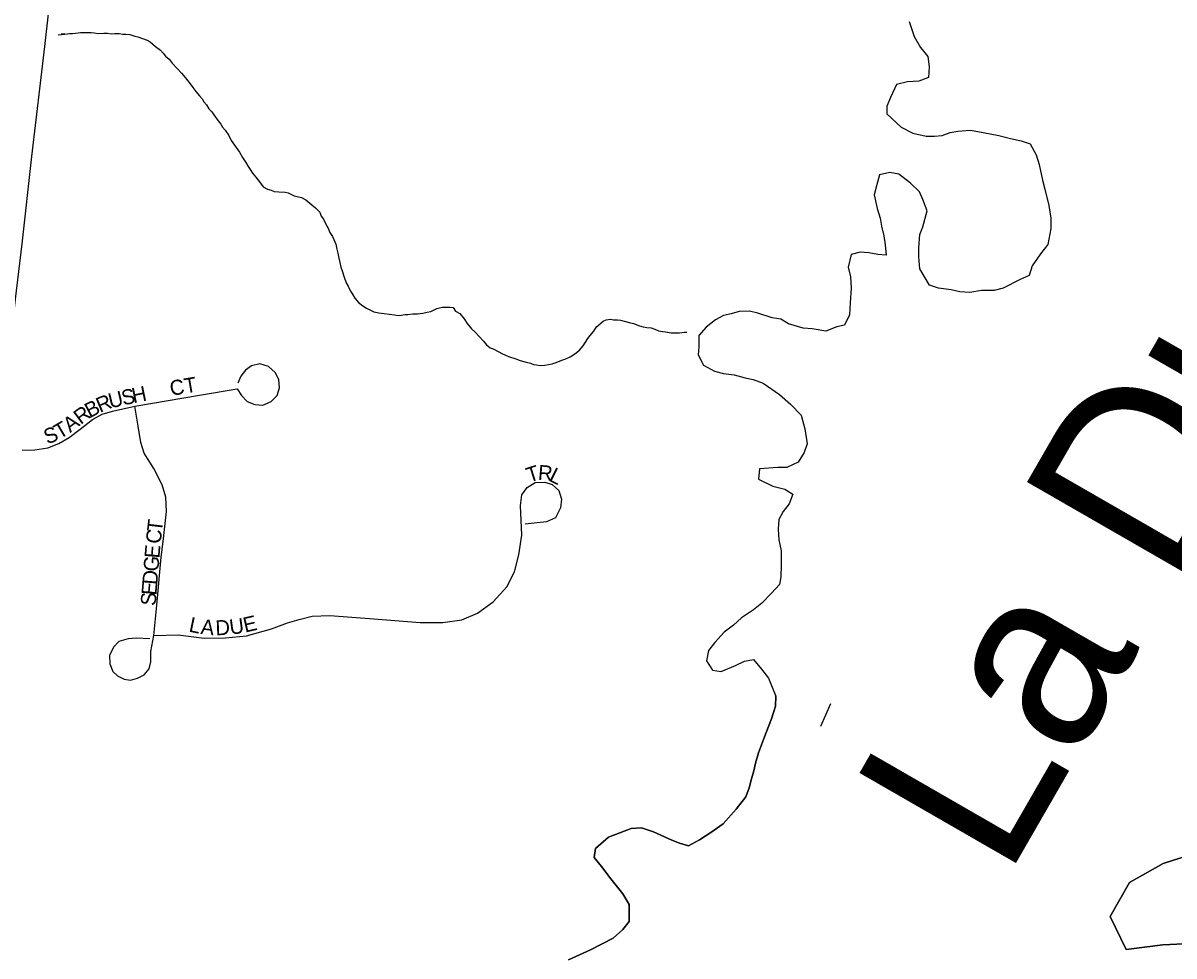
# Model space of a CAD drawing. Extents: x 0 to 34, y 0 to 22.
# Drawn here: x 3.05 to 3.775, y 16 to 16.588 of the extents above; entities that cross this region are included whole.
import ezdxf

# ---------------------------------------------------------------- set-up
doc = ezdxf.new("R2010")
doc.units = 0
for name, color, linetype in [('GM_X_Major_Lake', 7, 'Continuous'), ('GM_X_Major_Lake_Text', 7, 'Continuous'), ('GM_X_Major_River', 7, 'Continuous'), ('GM_X_Minor_River', 7, 'Continuous'), ('GM_X_Minor_River_Text', 7, 'Continuous'), ('GM_X_State_Route', 7, 'Continuous'), ('GM_X_Township_Subdivision', 7, 'Continuous'), ('GM_X_Township_Subdivision_Text', 7, 'Continuous')]:
    doc.layers.add(name, color=color, linetype=linetype)

msp = doc.modelspace()

# ---------------------------------------------------------------- linework, layer by layer
at = {"layer": 'GM_X_Major_Lake'}
for points in [[(3.60799, 16.58883), (3.61103, 16.57934), (3.6152, 16.5725), (3.61975, 16.56681), (3.62051, 16.56035), (3.62013, 16.55352), (3.61405, 16.55123), (3.60684, 16.55084), (3.60002, 16.54932), (3.59622, 16.54096), (3.59394, 16.53563), (3.59394, 16.5307), (3.60304, 16.52235), (3.61025, 16.51856), (3.6186, 16.51667), (3.62391, 16.51667), (3.62884, 16.51706), (3.63378, 16.51896), (3.63871, 16.51973), (3.64668, 16.5205), (3.65464, 16.51899), (3.66451, 16.5171), (3.67172, 16.51521), (3.67855, 16.5137), (3.68423, 16.5118), (3.68803, 16.50497), (3.68992, 16.49889), (3.69182, 16.48902), (3.69334, 16.48332), (3.69599, 16.47307), (3.69712, 16.46509), (3.69712, 16.45864), (3.69522, 16.44838), (3.69067, 16.44267), (3.68535, 16.43507), (3.68346, 16.42899), (3.67776, 16.42632), (3.66714, 16.42099), (3.66145, 16.41947), (3.65348, 16.41946), (3.64627, 16.41831), (3.63982, 16.41868), (3.63451, 16.41982), (3.62654, 16.42095), (3.62085, 16.42284), (3.61478, 16.43309), (3.61403, 16.44069), (3.61403, 16.44639), (3.61479, 16.45474), (3.61669, 16.45968), (3.61934, 16.46956), (3.61669, 16.47678), (3.61442, 16.48171), (3.60873, 16.48703), (3.60152, 16.49271), (3.59583, 16.49385), (3.58938, 16.49232), (3.58748, 16.48548), (3.58596, 16.47978), (3.58786, 16.47105), (3.58975, 16.46497), (3.59051, 16.46003), (3.59202, 16.45396), (3.59278, 16.44826), (3.59354, 16.4418), (3.58823, 16.44218), (3.58254, 16.44331)], [(3.58254, 16.44331), (3.57723, 16.44368), (3.57153, 16.44216), (3.56963, 16.43418), (3.57115, 16.4281), (3.57153, 16.42089), (3.57077, 16.41177), (3.57038, 16.40417), (3.56735, 16.39771), (3.56241, 16.39656), (3.55559, 16.39389), (3.54686, 16.3954), (3.54117, 16.39578), (3.53206, 16.39843), (3.52713, 16.40146), (3.52182, 16.40221), (3.51272, 16.40524), (3.50741, 16.40638), (3.50095, 16.40637), (3.49602, 16.40484), (3.49109, 16.4037), (3.48616, 16.40103), (3.48008, 16.39647), (3.47553, 16.39114), (3.47553, 16.38393), (3.47515, 16.37899), (3.47856, 16.37253), (3.48539, 16.36874), (3.49108, 16.36723), (3.49791, 16.36648), (3.50474, 16.36459), (3.50967, 16.36345), (3.51612, 16.36118), (3.52636, 16.35397), (3.53319, 16.3479), (3.54002, 16.34107), (3.54229, 16.33234), (3.5438, 16.32284), (3.54191, 16.31752), (3.53811, 16.31144), (3.5309, 16.30801), (3.52521, 16.30801), (3.51383, 16.30723), (3.51307, 16.30078), (3.52217, 16.29623), (3.52976, 16.29434), (3.53469, 16.2913), (3.53241, 16.28522), (3.52862, 16.28028), (3.52596, 16.27534), (3.52558, 16.26926), (3.52596, 16.26242), (3.52748, 16.25559), (3.52747, 16.24647), (3.52709, 16.23925), (3.52633, 16.23431), (3.5214, 16.22899), (3.51532, 16.22252), (3.51001, 16.21834), (3.50242, 16.21339), (3.49749, 16.20883), (3.49142, 16.20426), (3.48573, 16.1978), (3.48155, 16.19285), (3.48041, 16.18639), (3.4842, 16.18032), (3.48952, 16.17957), (3.49862, 16.18338), (3.50431, 16.18604), (3.51001, 16.18719), (3.51494, 16.18112), (3.51949, 16.17542), (3.52409, 16.16402)], [(3.52409, 16.16402), (3.52378, 16.15783)], [(3.52378, 16.15783), (3.52123, 16.14982), (3.51939, 16.14486), (3.51681, 16.13836), (3.51314, 16.12844), (3.51133, 16.12195), (3.51025, 16.117), (3.50879, 16.11204), (3.50734, 16.10632), (3.50514, 16.10059), (3.49916, 16.09291), (3.49094, 16.08369), (3.48305, 16.07827), (3.4759, 16.07362), (3.46913, 16.06973), (3.46343, 16.07156), (3.45848, 16.07339), (3.44705, 16.07857), (3.43944, 16.08113), (3.43301, 16.08067), (3.41868, 16.07517), (3.41043, 16.06822), (3.40974, 16.06251), (3.41435, 16.05687), (3.42012, 16.04896), (3.42781, 16.03956), (3.43168, 16.03277), (3.43181, 16.02213), (3.4277, 16.01714), (3.4217, 16.01174), (3.40739, 16.00434), (3.39345, 15.99808)], [(3.7896, 16.00846), (3.76764, 16.00742), (3.74456, 16.00446), (3.73447, 16.02523), (3.74672, 16.04667), (3.76779, 16.05872), (3.79006, 16.06585)]]:
    msp.add_lwpolyline(points, dxfattribs=at)
at = {"layer": 'GM_X_Major_River'}
for points in [[(3.60799, 16.58883), (3.61103, 16.57934), (3.6152, 16.5725), (3.61975, 16.56681), (3.62051, 16.56035), (3.62013, 16.55352), (3.61405, 16.55123), (3.60684, 16.55084), (3.60002, 16.54932), (3.59622, 16.54096), (3.59394, 16.53563), (3.59394, 16.5307), (3.60304, 16.52235), (3.61025, 16.51856), (3.6186, 16.51667), (3.62391, 16.51667), (3.62884, 16.51706), (3.63378, 16.51896), (3.63871, 16.51973), (3.64668, 16.5205), (3.65464, 16.51899), (3.66451, 16.5171), (3.67172, 16.51521), (3.67855, 16.5137), (3.68423, 16.5118), (3.68803, 16.50497), (3.68992, 16.49889), (3.69182, 16.48902), (3.69334, 16.48332), (3.69599, 16.47307), (3.69712, 16.46509), (3.69712, 16.45864), (3.69522, 16.44838), (3.69067, 16.44267), (3.68535, 16.43507), (3.68346, 16.42899), (3.67776, 16.42632), (3.66714, 16.42099), (3.66145, 16.41947), (3.65348, 16.41946), (3.64627, 16.41831), (3.63982, 16.41868), (3.63451, 16.41982), (3.62654, 16.42095), (3.62085, 16.42284), (3.61478, 16.43309), (3.61403, 16.44069), (3.61403, 16.44639), (3.61479, 16.45474), (3.61669, 16.45968), (3.61934, 16.46956), (3.61669, 16.47678), (3.61442, 16.48171), (3.60873, 16.48703), (3.60152, 16.49271), (3.59583, 16.49385), (3.58938, 16.49232), (3.58748, 16.48548), (3.58596, 16.47978), (3.58786, 16.47105), (3.58975, 16.46497), (3.59051, 16.46003), (3.59202, 16.45396), (3.59278, 16.44826), (3.59354, 16.4418), (3.58823, 16.44218), (3.58254, 16.44331)], [(3.58254, 16.44331), (3.57723, 16.44368), (3.57153, 16.44216), (3.56963, 16.43418), (3.57115, 16.4281), (3.57153, 16.42089), (3.57077, 16.41177), (3.57038, 16.40417), (3.56735, 16.39771), (3.56241, 16.39656), (3.55559, 16.39389), (3.54686, 16.3954), (3.54117, 16.39578), (3.53206, 16.39843), (3.52713, 16.40146), (3.52182, 16.40221), (3.51272, 16.40524), (3.50741, 16.40638), (3.50095, 16.40637), (3.49602, 16.40484), (3.49109, 16.4037), (3.48616, 16.40103), (3.48008, 16.39647), (3.47553, 16.39114), (3.47553, 16.38393), (3.47515, 16.37899), (3.47856, 16.37253), (3.48539, 16.36874), (3.49108, 16.36723), (3.49791, 16.36648), (3.50474, 16.36459), (3.50967, 16.36345), (3.51612, 16.36118), (3.52636, 16.35397), (3.53319, 16.3479), (3.54002, 16.34107), (3.54229, 16.33234), (3.5438, 16.32284), (3.54191, 16.31752), (3.53811, 16.31144), (3.5309, 16.30801), (3.52521, 16.30801), (3.51383, 16.30723), (3.51307, 16.30078), (3.52217, 16.29623), (3.52976, 16.29434), (3.53469, 16.2913), (3.53241, 16.28522), (3.52862, 16.28028), (3.52596, 16.27534), (3.52558, 16.26926), (3.52596, 16.26242), (3.52748, 16.25559), (3.52747, 16.24647), (3.52709, 16.23925), (3.52633, 16.23431), (3.5214, 16.22899), (3.51532, 16.22252), (3.51001, 16.21834), (3.50242, 16.21339), (3.49749, 16.20883), (3.49142, 16.20426), (3.48573, 16.1978), (3.48155, 16.19285), (3.48041, 16.18639), (3.4842, 16.18032), (3.48952, 16.17957), (3.49862, 16.18338), (3.50431, 16.18604), (3.51001, 16.18719), (3.51494, 16.18112), (3.51949, 16.17542), (3.52409, 16.16402)], [(3.52378, 16.15783), (3.52409, 16.16402)], [(3.39345, 15.99808), (3.40739, 16.00434), (3.4217, 16.01174), (3.4277, 16.01714), (3.43181, 16.02213), (3.43168, 16.03277), (3.42781, 16.03956), (3.42012, 16.04896), (3.41435, 16.05687), (3.40974, 16.06251), (3.41043, 16.06822), (3.41868, 16.07517), (3.43301, 16.08067), (3.43944, 16.08113), (3.44705, 16.07857), (3.45848, 16.07339), (3.46343, 16.07156), (3.46913, 16.06973), (3.4759, 16.07362), (3.48305, 16.07827), (3.49094, 16.08369), (3.49916, 16.09291), (3.50514, 16.10059), (3.50734, 16.10632), (3.50879, 16.11204), (3.51025, 16.117), (3.51133, 16.12195), (3.51314, 16.12844), (3.51681, 16.13836), (3.51939, 16.14486), (3.52123, 16.14982), (3.52378, 16.15783)], [(3.79006, 16.06585), (3.76779, 16.05872), (3.74672, 16.04667), (3.73447, 16.02523), (3.74456, 16.00446), (3.76764, 16.00742), (3.7896, 16.00846)]]:
    msp.add_lwpolyline(points, dxfattribs=at)
at = {"layer": 'GM_X_Minor_River'}
for points in [[(3.07218, 16.58046), (3.07635, 16.58093), (3.07407, 16.58088), (3.07635, 16.58093), (3.07938, 16.58137), (3.08129, 16.58142), (3.08319, 16.58146), (3.08622, 16.5819), (3.0885, 16.58195), (3.09078, 16.582), (3.09307, 16.58205), (3.09497, 16.58171), (3.09764, 16.58139), (3.10107, 16.58146), (3.10335, 16.58151), (3.10564, 16.58118), (3.10792, 16.58123), (3.11058, 16.58129), (3.11287, 16.58096), (3.11477, 16.581), (3.11744, 16.58068), (3.12051, 16.57961), (3.12241, 16.57927), (3.12817, 16.57711), (3.13009, 16.57601), (3.13358, 16.57305), (3.13667, 16.57084), (3.13823, 16.56897), (3.13979, 16.5671), (3.14211, 16.56525), (3.14407, 16.56264), (3.14719, 16.55928), (3.14991, 16.5563), (3.15225, 16.55369), (3.15382, 16.55145), (3.15538, 16.54958), (3.15695, 16.54734), (3.15891, 16.54472), (3.16125, 16.54211), (3.16281, 16.54024), (3.16399, 16.53837), (3.16555, 16.5365), (3.16713, 16.53387), (3.16907, 16.53202), (3.17025, 16.53014), (3.17299, 16.5264), (3.17456, 16.52416), (3.17574, 16.52228), (3.1773, 16.52041), (3.17966, 16.51705), (3.18124, 16.51404), (3.18321, 16.51104), (3.18635, 16.50655), (3.18832, 16.50317), (3.19029, 16.50017), (3.19187, 16.49755), (3.19305, 16.49567), (3.19462, 16.49343), (3.19657, 16.49081), (3.19814, 16.48894), (3.1997, 16.48708), (3.20127, 16.48483), (3.20396, 16.48337), (3.20626, 16.48266), (3.20818, 16.48194), (3.21123, 16.48163), (3.21504, 16.48133), (3.21694, 16.48099), (3.22079, 16.47917), (3.22347, 16.47847), (3.22537, 16.47814), (3.22807, 16.47667), (3.23194, 16.47334), (3.23427, 16.47149), (3.23698, 16.46889), (3.2378, 16.46624), (3.23936, 16.46438), (3.24056, 16.46174), (3.24215, 16.45874), (3.24334, 16.4561), (3.24492, 16.45348), (3.24572, 16.4516), (3.24693, 16.44858), (3.24775, 16.44556), (3.24819, 16.44291), (3.24901, 16.43988), (3.24945, 16.43723), (3.25028, 16.43421), (3.25108, 16.43195), (3.25231, 16.42779), (3.25353, 16.4244), (3.25472, 16.42215), (3.2563, 16.41914), (3.25748, 16.41727), (3.25906, 16.41464), (3.2614, 16.41203), (3.26411, 16.40981), (3.26642, 16.40834), (3.26835, 16.40724), (3.27103, 16.40616), (3.27409, 16.40547)], [(3.27409, 16.40547), (3.28401, 16.40416), (3.2863, 16.40383), (3.2882, 16.40387), (3.29047, 16.4043), (3.29237, 16.40434), (3.29541, 16.40479), (3.29845, 16.40485), (3.30186, 16.40531), (3.30452, 16.40575), (3.30679, 16.40617), (3.31055, 16.40816), (3.31396, 16.40899), (3.31586, 16.40903), (3.3189, 16.4091), (3.32081, 16.40876), (3.32238, 16.40651), (3.32507, 16.40505), (3.32781, 16.40169), (3.32977, 16.39869), (3.33251, 16.39533), (3.33445, 16.39348), (3.33718, 16.39049), (3.3399, 16.38751), (3.34185, 16.38528), (3.34417, 16.38343), (3.34609, 16.38271), (3.34955, 16.38088), (3.35148, 16.37978), (3.3534, 16.37907), (3.3557, 16.37798), (3.3603, 16.37656), (3.36298, 16.37547), (3.36681, 16.37442), (3.36949, 16.37371), (3.37141, 16.37299), (3.37331, 16.37266), (3.3756, 16.37233), (3.37864, 16.37239), (3.38092, 16.37282), (3.38319, 16.37325), (3.38584, 16.37407), (3.38923, 16.37567), (3.39187, 16.37648), (3.39451, 16.37768), (3.39751, 16.37964), (3.4005, 16.38199), (3.40273, 16.3847), (3.4042, 16.38701), (3.40567, 16.38932), (3.40715, 16.39125), (3.40938, 16.39396), (3.41122, 16.39666), (3.41533, 16.40017), (3.41722, 16.40097), (3.41987, 16.40141), (3.42178, 16.40107), (3.42444, 16.40113), (3.42635, 16.40079), (3.43171, 16.39939), (3.43438, 16.39869), (3.43822, 16.39725), (3.44052, 16.39654), (3.44281, 16.39621), (3.44548, 16.39589), (3.44777, 16.39518), (3.45008, 16.39409), (3.45275, 16.39377), (3.45466, 16.39343), (3.45809, 16.39274), (3.46, 16.39278), (3.46342, 16.39286), (3.46645, 16.3933), (3.46797, 16.39334)]]:
    msp.add_lwpolyline(points, dxfattribs=at)
at = {"layer": 'GM_X_Minor_River_Text'}
msp.add_lwpolyline([(3.55234, 16.14511), (3.5587, 16.15938)], dxfattribs=at)
at = {"layer": 'GM_X_State_Route'}
msp.add_lwpolyline([(2.9188, 15.93475), (2.92754, 15.95695), (2.94923, 16.01129), (2.97844, 16.08453), (2.99434, 16.12448), (3.00809, 16.15949), (3.01517, 16.1799), (3.01968, 16.19665), (3.02312, 16.21792), (3.0287, 16.26388), (3.03193, 16.29266), (3.03472, 16.31908), (3.04541, 16.41411), (3.04959, 16.44884), (3.05568, 16.50388), (3.06377, 16.57313), (3.06614, 16.59382)], dxfattribs=at)
at = {"layer": 'GM_X_Township_Subdivision'}
for points in [[(3.04954, 16.31886), (3.05749, 16.31908), (3.06565, 16.32037), (3.07274, 16.32316), (3.07918, 16.32703), (3.08605, 16.33218), (3.09378, 16.3382), (3.10001, 16.34163), (3.10646, 16.34357), (3.12042, 16.34657), (3.16123, 16.35366), (3.18485, 16.35753), (3.18765, 16.35345), (3.1913, 16.34958), (3.19602, 16.34765), (3.20118, 16.34722), (3.20633, 16.34958), (3.2102, 16.35345), (3.21149, 16.35817), (3.21106, 16.36354), (3.20891, 16.36784), (3.20461, 16.3717), (3.19924, 16.37342), (3.19388, 16.37213), (3.19022, 16.36934), (3.18722, 16.36547), (3.18528, 16.36118)], [(3.12987, 16.20009), (3.12128, 16.20052), (3.11634, 16.20009), (3.11032, 16.19837), (3.10732, 16.19515), (3.10452, 16.18978), (3.10474, 16.18441), (3.10667, 16.17968), (3.10968, 16.17689), (3.11376, 16.17474), (3.11784, 16.1741), (3.12214, 16.17539), (3.12643, 16.17754), (3.12944, 16.18119), (3.13051, 16.1857), (3.13051, 16.19214), (3.13245, 16.20224), (3.13416, 16.21899), (3.13717, 16.25164), (3.13827, 16.26149), (3.14039, 16.28042), (3.13996, 16.28944), (3.1376, 16.29717), (3.13245, 16.30748), (3.12643, 16.31715), (3.12428, 16.3238), (3.12257, 16.33411), (3.12042, 16.34657)], [(3.13245, 16.20224), (3.1477, 16.20267), (3.16423, 16.20052), (3.17755, 16.20073), (3.19087, 16.20202), (3.20655, 16.20653), (3.21664, 16.21018), (3.22395, 16.21233), (3.23211, 16.21448), (3.24328, 16.21491), (3.27098, 16.21276), (3.30019, 16.2104), (3.31437, 16.2104), (3.3264, 16.21212), (3.33628, 16.21641), (3.34616, 16.2235), (3.35475, 16.23295), (3.35948, 16.2424), (3.36227, 16.25314), (3.3642, 16.26538), (3.36334, 16.28407), (3.3642, 16.29073), (3.36742, 16.29545), (3.37258, 16.29867), (3.37859, 16.29889), (3.38332, 16.29739), (3.3874, 16.29352), (3.38912, 16.28815), (3.38847, 16.28257), (3.38525, 16.27634), (3.37966, 16.27376), (3.37193, 16.2729), (3.36613, 16.27226)]]:
    msp.add_lwpolyline(points, dxfattribs=at)

# ---------------------------------------------------------------- texts
at = {"layer": 'GM_X_Major_Lake_Text'}
msp.add_text('La Due', height=0.113717, rotation=60.0665, dxfattribs=at).set_placement((3.66902, 16.04815))
at = {"layer": 'GM_X_Township_Subdivision_Text'}
for s, rotation, p in [('CT', 9.4702, (3.14332, 16.35312)), ('U', 13.54845, (3.10506, 16.34518)), ('S', 11.72259, (3.11308, 16.34711)), ('H', 11.63993, (3.1196, 16.34847)), ('B', 27.93389, (3.09211, 16.33898)), ('R', 22.77121, (3.09853, 16.3424)), ('A', 37.21859, (3.07978, 16.32971)), ('R', 36.43272, (3.08639, 16.33473)), ('S', 21.42594, (3.06536, 16.32249)), ('T', 30.61873, (3.07305, 16.32565)), ('T', 17.65723, (3.36866, 16.29838)), ('R', 355.50258, (3.37405, 16.30029)), ('L', 333.3372, (3.3806, 16.29996)), ('T', 83.31889, (3.13749, 16.26708)), ('C', 83.98972, (3.13671, 16.25965)), ('E', 85.3418, (3.13595, 16.25058)), ('G', 85.29624, (3.13527, 16.24226)), ('D', 85.31802, (3.13459, 16.23396)), ('E', 85.30273, (3.13404, 16.22731)), ('S', 85.32257, (3.1335, 16.22067)), ('L', 348.33646, (3.15407, 16.20476)), ('A', 353.98875, (3.16161, 16.20325)), ('D', 2.33723, (3.1714, 16.20233)), ('U', 7.68956, (3.18068, 16.20275)), ('E', 12.99685, (3.18989, 16.20404))]:
    msp.add_text(s, height=0.00947, rotation=rotation, dxfattribs=at).set_placement(p)

doc.saveas('drawing.dxf')
